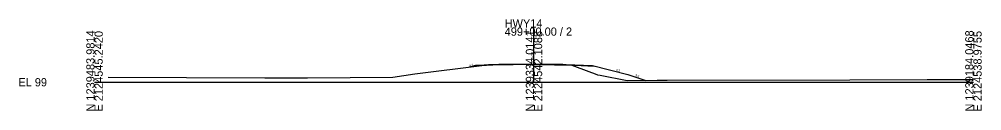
# Model space of a CAD drawing. Extents: x -26 to 303, y -10 to 11521.
# Drawn here: x -25.7 to 302.8, y 10490.3 to 10521.5 of the extents above; entities that cross this region are included whole.
import ezdxf

# ---------------------------------------------------------------- set-up
doc = ezdxf.new("R2010")
doc.units = 0
for name, color, linetype in [('XS_CELL', 7, 'Continuous'), ('XS_P_FINISHED_GRADE', 7, 'Continuous'), ('XS_P_SUBGRADE_GRANULAR', 7, 'Continuous'), ('XS_P_SUBGRADE_LEVELING', 7, 'Continuous'), ('XS_P_TX_FS_BS', 7, 'Continuous'), ('XS_X_GROUND', 7, 'Continuous'), ('XS_X_GROUND_TX', 7, 'Continuous')]:
    doc.layers.add(name, color=color, linetype=linetype)

msp = doc.modelspace()

# ---------------------------------------------------------------- linework, layer by layer
at = {"layer": 'XS_CELL'}
for p, q in [((150, 10500), (150, 10518.66)), ((0, 10500), (150, 10500)), ((150, 10500), (300, 10500))]:
    msp.add_line(p, q, dxfattribs=at)
at = {"layer": 'XS_P_FINISHED_GRADE'}
for p, q in [((130, 10505.69), (128.02, 10505.2)), ((136, 10505.93), (130, 10505.69)), ((150, 10506.21), (136, 10505.93)), ((150, 10506.21), (164, 10505.93)), ((164, 10505.93), (170, 10505.69)), ((170, 10505.69), (182, 10502.69)), ((182, 10502.69), (188.13, 10500.65))]:
    msp.add_line(p, q, dxfattribs=at)
at = {"layer": 'XS_P_SUBGRADE_GRANULAR'}
for p, q in [((136, 10505.81), (129.4, 10505.54)), ((164, 10505.81), (170.6, 10505.54))]:
    msp.add_line(p, q, dxfattribs=at)
at = {"layer": 'XS_P_SUBGRADE_LEVELING'}
for p, q in [((150, 10506.09), (136, 10505.81)), ((136, 10505.81), (136, 10505.93)), ((150, 10506.09), (164, 10505.81)), ((164, 10505.81), (164, 10505.93))]:
    msp.add_line(p, q, dxfattribs=at)
at = {"layer": 'XS_X_GROUND'}
for p, q in [((109.32, 10502.84), (132.25, 10505.73)), ((132.25, 10505.73), (134.53, 10506.02)), ((134.53, 10506.02), (137.97, 10506.21)), ((137.97, 10506.21), (144.57, 10506.21)), ((144.57, 10506.21), (150, 10506.21)), ((150, 10506.21), (159.83, 10506.22)), ((159.83, 10506.22), (162.28, 10505.95)), ((162.28, 10505.95), (162.92, 10505.88)), ((162.92, 10505.88), (168.77, 10503.68)), ((168.77, 10503.68), (170.87, 10502.9)), ((4.68, 10501.7), (58.14, 10501.55)), ((58.14, 10501.55), (67.79, 10501.52)), ((67.79, 10501.52), (72.68, 10501.51)), ((72.68, 10501.51), (101.79, 10501.79)), ((101.79, 10501.79), (109.32, 10502.84)), ((170.87, 10502.9), (171.72, 10502.58)), ((171.72, 10502.58), (172.58, 10502.41)), ((172.58, 10502.41), (181.81, 10500.57)), ((181.81, 10500.57), (192.07, 10500.7)), ((192.07, 10500.7), (192.51, 10500.71)), ((192.51, 10500.71), (195.44, 10500.72)), ((195.44, 10500.72), (257.76, 10500.85)), ((257.76, 10500.85), (284.18, 10500.89)), ((284.18, 10500.89), (300, 10500.99))]:
    msp.add_line(p, q, dxfattribs=at)

# ---------------------------------------------------------------- texts
at = {"layer": 'XS_CELL'}
for s, p in [('HWY14', (140, 10518.66)), ('499+00.00 / 2', (140, 10515.86)), ('EL 99', (-26, 10498.6))]:
    msp.add_text(s, height=2.8, dxfattribs=at).set_placement(p)
for s, p in [('N 1239483.9814', (0, 10490)), ('E 2124545.2420', (2.8, 10490)), ('N 1239334.0141', (150, 10490)), ('E 2124542.1088', (152.8, 10490)), ('N 1239184.0468', (300, 10490)), ('E 2124538.9755', (302.8, 10490))]:
    msp.add_text(s, height=2.8, rotation=90, dxfattribs=at).set_placement(p)
at = {"layer": 'XS_P_TX_FS_BS'}
for s, rotation, p in [('4:1', 14.0362, (127.91, 10505.27)), ('4:1', 345.9638, (177.87, 10503.9)), ('3:1', 341.5651, (184.47, 10502.13))]:
    msp.add_text(s, height=0.8, rotation=rotation, dxfattribs=at).set_placement(p)
at = {"layer": 'XS_X_GROUND_TX'}
msp.add_text('105.21', height=1, rotation=90, dxfattribs=at).set_placement((150, 10506.31))

doc.saveas('drawing.dxf')
